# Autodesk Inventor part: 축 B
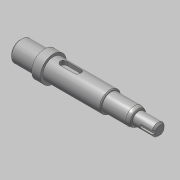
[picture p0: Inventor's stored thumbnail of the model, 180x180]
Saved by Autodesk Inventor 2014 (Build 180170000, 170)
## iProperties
Created: 2020-04
Part Number: 축 B
Material: 강철, 연강
Document SubType Name: Modeling
Designer: mduedu
Density: 7.86 g/cm^3
Appearance: 강철
Mass: 60.8598 g
Surface Area: 31.2859 cm^2
Volume: 7.74298 cm^3
Author: mduedu
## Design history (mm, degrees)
sketch "스케치1"
  geometry: L1 (0, 0)-(14, 0); L2 (14, 0)-(14, 6); L3 (14, 6)-(0, 6); L4 (0, 6)-(0, 0); L5 (14, 0)-(19, 0); L6 (19, 0)-(19, 7.5); L7 (19, 7.5)-(14, 7.5); L8 (14, 7.5)-(14, 0); L9 (19, 0)-(52, 0); L10 (52, 0)-(52, 6); L11 (52, 6)-(19, 6); L12 (19, 6)-(19, 0); L13 (52, 0)-(68, 0); L14 (68, 0)-(68, 5); L15 (68, 5)-(52, 5); L16 (52, 5)-(52, 0); L17 (68, 0)-(80, 0); L18 (80, 0)-(80, 3.5); L19 (80, 3.5)-(68, 3.5); L20 (68, 3.5)-(68, 0)
  constraints: 40 end point, 10 parallel, 5 horizontal, 5 perpendicular
  dimensions: "d0" = 80 distance between parallel lines of L18 L4; "d2" = 14 distance of L2.end L3.end; "d3" = 5 distance of L6.end L7.end; "d5" = 7 diameter of L19 L17; "d6" = 10 diameter of L15 L13; "d7" = 12 diameter of L11 L9; "d8" = 12 diameter of L3 L1; "d9" = 15 diameter of L7 L5; "d35" = 16 distance of L14.end L15.end; "d36" = 52 distance between parallel lines of L10 L4
revolve "회전1" sketch "스케치1" stored, may be unused: angle "d11" = 90 deg
sketch "스케치2"
  geometry: L1 (0, 6)-(0, -6) reference; L2 (0, -6)-(-14, -6) reference; L3 (-14, -6)-(-14, -7.5) reference; L4 (-14, -7.5)-(-19, -7.5) reference; L5 (-19, -7.5)-(-19, -6) reference; L6 (-19, -6)-(-52, -6) reference; L7 (-52, -6)-(-52, -5) reference; L8 (-52, -5)-(-68, -5) reference; L9 (-68, -5)-(-68, -3.5) reference; L10 (-68, -3.5)-(-80, -3.5) reference; L11 (-80, -3.5)-(-80, 3.5) reference; L12 (-80, 3.5)-(-68, 3.5) reference; L13 (-68, 3.5)-(-68, 5) reference; L14 (-68, 5)-(-52, 5) reference; L15 (-52, 5)-(-52, 6) reference; L16 (-52, 6)-(-19, 6) reference; L17 (-19, 6)-(-19, 7.5) reference; L18 (-19, 7.5)-(-14, 7.5) reference; L19 (-14, 7.5)-(-14, 6) reference; L20 (-14, 6)-(0, 6) reference; L21 (-80, 3.5)-(-72, 3.5); L22 (-72, 3.5)-(-72, 2.3); L23 (-72, 2.3)-(-80, 2.3); L24 (-80, 2.3)-(-80, 3.5); 1 further point
  constraints: 8 end point, 2 parallel, 1 horizontal, 1 perpendicular
  dimensions: "d37" = 8 distance of L22.end L23.end; "d38" = 1.2 distance of L21.end L22.end
extrude "돌출1" cut sketch "스케치2" stored distance "d14" = 2; taper "d15" = 0 deg
fillet "모깎기1" dims "d16" = 1
sketch "스케치3"
  geometry: L1 (0, -6)-(0, 6) reference; L2 (0, 6)-(14, 6) reference; L3 (14, 6)-(14, 7.5) reference; L4 (14, 7.5)-(19, 7.5) reference; L5 (19, 7.5)-(19, 6) reference; L6 (19, 6)-(52, 6) reference; L7 (52, 6)-(52, 5) reference; L8 (52, 5)-(68, 5) reference; L9 (68, 5)-(68, 3.5) reference; L10 (68, 3.5)-(80, 3.5) reference; L11 (80, 3.5)-(80, -3.5) reference; L12 (80, -3.5)-(68, -3.5) reference; L13 (68, -3.5)-(68, -5) reference; L14 (68, -5)-(52, -5) reference; L15 (52, -5)-(52, -6) reference; L16 (52, -6)-(19, -6) reference; L17 (19, -6)-(19, -7.5) reference; L18 (19, -7.5)-(14, -7.5) reference; L19 (14, -7.5)-(14, -6) reference; L20 (14, -6)-(0, -6) reference; L21 (23, 6)-(35, 6); L22 (35, 6)-(35, 3.5); L23 (35, 3.5)-(23, 3.5); L24 (23, 3.5)-(23, 6); 1 further point
  constraints: 8 end point, 2 parallel, 1 horizontal, 1 perpendicular, 1 point on line
  dimensions: "d17" = 12 distance of L22.end L23.end; "d18" = 2.5 distance of L21.end L22.end; "d19" = 4 distance from line of L24 L4.end
extrude "돌출2" cut sketch "스케치3" stored distance "d20" = 4; taper "d21" = 0 deg
fillet "모깎기2" dims "d22" = 2
chamfer "모따기1" distance "d23" = 1; stored, may be unused: second distance "d24" = 2, angle "d25" = 45 deg
chamfer "모따기2" distance "d26" = 0.5; stored, may be unused: second distance "d27" = 2, angle "d28" = 45 deg
fillet "모깎기3" dims "d29" = 0.3
chamfer "모따기3" distance "d30" = 1.39; stored, may be unused: second distance "d31" = 2, angle "d32" = 30 deg
fillet "모깎기4" dims "d33" = 4, "d34" = 0.5
node "솔리드1"
node "절단 모서리 투영2"
node "절단 모서리 투영3"
